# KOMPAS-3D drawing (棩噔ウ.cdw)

Referenced files in D:\по учебе\тп АКТ\: Чертеж.cdw
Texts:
  Штамп для  двухугловой гибки
  Олечка
  домик
  Текст на чертеже
  Размерные надписи
  Шероховатость
  Линия-выноска #1
  Линия-выноска #2
  Линия-выноска #3
  Отклонения формы и база
  Заголовок таблицы
  Ячейка таблицы
  Стрелка вида
  Обозначение изменения
  Фигурная скобка
  Номер узла
  Марка координационной оси
  VRCB
  Выносная надпись
  Обозначение узла
  Марка/позиционное обозначение с линией-выноской
  Марка/позиционное обозначение на линии
  Марка/позиционное обозначение без линии-выноски
  Normal
  План верха
  Операционный эскиз
  Заготовка
  1. Параметры плит: верхняя - 160х125х45мм
  2. Перпендикулярность колонок - 0,02мм
  3. Установить на пресс ЭР50
  4. Усилие гиба 9кН
  5. Рабочий ход ползуна пресса 70мм
  6. Работать при двуручном усилии пресса
  7. Заготовку подавать на фиксаторы
  8. Штампуемой деталь удалить пинцетом
  9. Маркировать обозначение штампа
  10. Маркировать обозначение детали
  1. Материал: сталь 0,8 кП
  2. Усилие пресса: 9кН
  Штамп для
  двухугловой гибки
  Громова Е.Г.
  СГАУ гр.1403
  Сборочный чертеж
Dimensions and other numbers on the sheet: 103ПК01.6512.002.000.СБ; 7; 15; 14; 1; 2; 3; 4; 5; 6; 18; 17; 8; 16; 9; 10; 11; 12; 13; 250; 190; 205; 43; 32; 160; 4 отв.; 22; 30; 76,4; 56,22; 1 переход; 140; 80; 54; 82; 1:1; 103ПК01.6512.002.000-; 0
